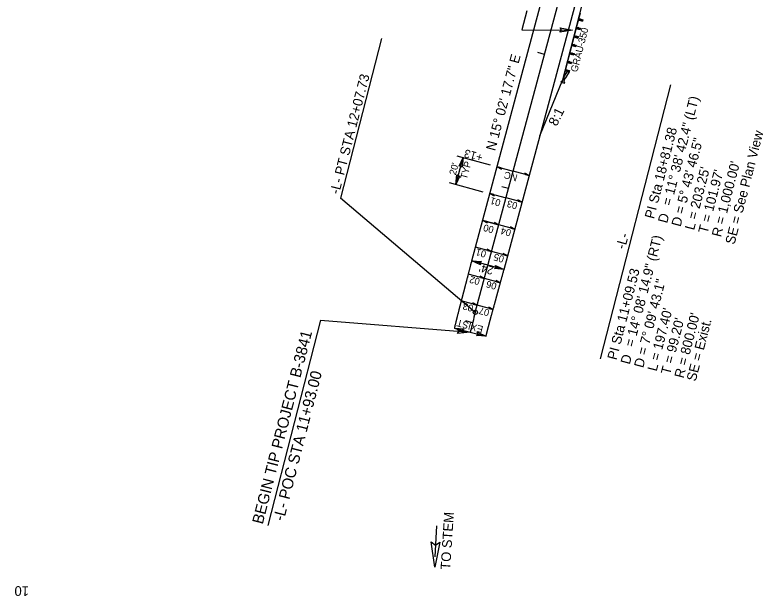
# Model space of a CAD drawing. Extents: x 2078889 to 2079501, y 925860 to 927219.
# Drawn here: x 2078889 to 2079428, y 925860 to 926279 of the extents above; entities that cross this region are included whole.
import ezdxf

# ---------------------------------------------------------------- set-up
doc = ezdxf.new("R2010")
doc.units = 0
for name, color, linetype in [('Default', 7, 'Continuous'), ('Prop Dimension Text', 7, 'Continuous'), ('Prop DSN Text', 7, 'Continuous'), ('Prop EOT', 7, 'Continuous'), ('Prop Guardrail Anchor Unit CELL', 7, 'Continuous'), ('Prop Horizontal Alignment', 7, 'Continuous'), ('Prop Horizontal Alignment Curve and Spiral Data', 7, 'Continuous'), ('Prop Horizontal Alignment Direction Label', 7, 'Continuous'), ('Prop Horizontal Alignment Station Label', 7, 'Continuous'), ('Prop Horizontal Alignment Tick Label', 7, 'Continuous'), ('Prop Horizontal Alignment Tick Small', 7, 'Continuous'), ('Prop Paved Shoulder', 7, 'Continuous'), ('Prop Superelevation  Arrow CELL', 7, 'Continuous'), ('Prop Superelevation Label', 7, 'Continuous'), ('Prop Terminator CELL', 7, 'Continuous'), ('Scratch_Level_1', 7, 'Continuous')]:
    doc.layers.add(name, color=color, linetype=linetype)

msp = doc.modelspace()

# ---------------------------------------------------------------- linework, layer by layer
at = {"layer": 'Prop Dimension Text'}
for p, q in [((2079257.42, 926281.53), (2079253.89, 926267.81)), ((2079253.89, 926267.81), (2079290.34, 926267.6)), ((2079206.31, 926156.54), (2079211.43, 926175.87)), ((2079207.09, 926177.04), (2079230.95, 926170.63)), ((2079201.36, 926157.87), (2079225.76, 926151.31)), ((2079241.03, 926095.44), (2079217.85, 926101.67))]:
    msp.add_line(p, q, dxfattribs=at)
at = {"layer": 'Prop DSN Text'}
msp.add_line((2079205.34, 926053.03), (2079228, 926047.39), dxfattribs=at)
at = {"layer": 'Prop EOT'}
for p, q in [((2079217.85, 926101.67), (2079301.07, 926411.43)), ((2079241.03, 926095.44), (2079324.25, 926405.2))]:
    msp.add_line(p, q, dxfattribs=at)
for points in [[(2079205.34, 926053.03), (2079205.5, 926053.7), (2079205.66, 926054.37), (2079205.82, 926055.03), (2079205.98, 926055.7), (2079206.15, 926056.36), (2079206.31, 926057.03), (2079206.47, 926057.7), (2079206.64, 926058.36), (2079206.8, 926059.03), (2079206.97, 926059.69), (2079207.14, 926060.36), (2079207.3, 926061.02), (2079207.47, 926061.69), (2079207.64, 926062.35), (2079207.81, 926063.02), (2079207.98, 926063.68), (2079208.15, 926064.34), (2079208.32, 926065.01), (2079208.49, 926065.67), (2079208.66, 926066.34), (2079208.83, 926067), (2079209, 926067.66), (2079209.17, 926068.32), (2079209.34, 926068.97), (2079209.51, 926069.62), (2079209.68, 926070.28), (2079209.85, 926070.93), (2079210.02, 926071.58), (2079210.19, 926072.24), (2079210.36, 926072.89), (2079210.53, 926073.55), (2079210.7, 926074.2), (2079210.87, 926074.85), (2079211.04, 926075.51), (2079211.21, 926076.16), (2079211.38, 926076.82), (2079211.55, 926077.47), (2079211.72, 926078.12), (2079211.89, 926078.78), (2079212.06, 926079.43), (2079212.23, 926080.09), (2079212.4, 926080.74), (2079212.57, 926081.39), (2079212.74, 926082.05), (2079212.91, 926082.7), (2079213.08, 926083.36), (2079213.25, 926084.01), (2079213.42, 926084.66), (2079213.59, 926085.32), (2079213.76, 926085.97), (2079213.94, 926086.63), (2079214.11, 926087.28), (2079214.28, 926087.93), (2079214.45, 926088.59), (2079214.62, 926089.24), (2079214.79, 926089.9), (2079214.96, 926090.55), (2079215.13, 926091.2), (2079215.3, 926091.86), (2079215.47, 926092.51), (2079215.64, 926093.16), (2079215.81, 926093.82), (2079215.98, 926094.47), (2079216.15, 926095.13), (2079216.32, 926095.78), (2079216.49, 926096.43), (2079216.66, 926097.09), (2079216.83, 926097.74), (2079217, 926098.4), (2079217.17, 926099.05), (2079217.34, 926099.7), (2079217.51, 926100.36), (2079217.85, 926101.67)], [(2079228, 926047.39), (2079228.16, 926048.04), (2079228.33, 926048.68), (2079228.49, 926049.33), (2079228.66, 926049.97), (2079228.83, 926050.61), (2079228.99, 926051.26), (2079229.16, 926051.9), (2079229.33, 926052.55), (2079229.5, 926053.19), (2079229.67, 926053.84), (2079229.84, 926054.48), (2079230.01, 926055.12), (2079230.18, 926055.77), (2079230.35, 926056.41), (2079230.52, 926057.05), (2079230.69, 926057.7), (2079230.87, 926058.34), (2079231.04, 926058.98), (2079231.22, 926059.62), (2079231.39, 926060.27), (2079231.57, 926060.91), (2079231.74, 926061.55), (2079231.92, 926062.2), (2079232.1, 926062.86), (2079232.28, 926063.51), (2079232.46, 926064.16), (2079232.63, 926064.81), (2079232.81, 926065.46), (2079232.99, 926066.11), (2079233.17, 926066.77), (2079233.35, 926067.42), (2079233.53, 926068.07), (2079233.71, 926068.72), (2079233.88, 926069.37), (2079234.06, 926070.02), (2079234.24, 926070.68), (2079234.42, 926071.33), (2079234.6, 926071.98), (2079234.78, 926072.63), (2079234.96, 926073.28), (2079235.13, 926073.93), (2079235.31, 926074.59), (2079235.49, 926075.24), (2079235.67, 926075.89), (2079235.85, 926076.54), (2079236.03, 926077.19), (2079236.2, 926077.84), (2079236.38, 926078.5), (2079236.56, 926079.15), (2079236.74, 926079.8), (2079236.92, 926080.45), (2079237.1, 926081.1), (2079237.28, 926081.75), (2079237.45, 926082.41), (2079237.63, 926083.06), (2079237.81, 926083.71), (2079237.99, 926084.36), (2079238.17, 926085.01), (2079238.35, 926085.66), (2079238.53, 926086.32), (2079238.7, 926086.97), (2079238.88, 926087.62), (2079239.06, 926088.27), (2079239.24, 926088.92), (2079239.42, 926089.57), (2079239.6, 926090.23), (2079239.78, 926090.88), (2079239.95, 926091.53), (2079240.13, 926092.18), (2079240.31, 926092.83), (2079240.49, 926093.48), (2079240.67, 926094.14), (2079241.03, 926095.44)]]:
    msp.add_spline(points, degree=3, dxfattribs=at)
at = {"layer": 'Prop Guardrail Anchor Unit CELL'}
for p, q in [((2079295.4, 926278.34), (2079283.58, 926233.11)), ((2079294.76, 926275.88), (2079294.51, 926274.92)), ((2079296.21, 926275.5), (2079294.51, 926274.92)), ((2079294.76, 926275.88), (2079297.66, 926275.13)), ((2079295.96, 926274.54), (2079294.76, 926275.88)), ((2079296.21, 926275.5), (2079295.96, 926274.54)), ((2079297.41, 926274.16), (2079296.21, 926275.5)), ((2079294.51, 926274.92), (2079297.41, 926274.16)), ((2079294.51, 926274.92), (2079295.96, 926274.54)), ((2079295.96, 926274.54), (2079297.66, 926275.13)), ((2079297.66, 926275.13), (2079297.41, 926274.16)), ((2079294.64, 926269.4), (2079292.91, 926268.82)), ((2079292.91, 926268.82), (2079295.87, 926268.05)), ((2079293.16, 926269.79), (2079296.12, 926269.02)), ((2079293.16, 926269.79), (2079294.39, 926268.43)), ((2079294.64, 926269.4), (2079294.39, 926268.43)), ((2079294.39, 926268.43), (2079296.12, 926269.02)), ((2079295.87, 926268.05), (2079294.64, 926269.4)), ((2079296.12, 926269.02), (2079295.87, 926268.05)), ((2079293.05, 926263.31), (2079291.32, 926262.72)), ((2079291.32, 926262.72), (2079294.27, 926261.95)), ((2079291.57, 926263.69), (2079294.52, 926262.92)), ((2079291.57, 926263.69), (2079292.79, 926262.34)), ((2079293.05, 926263.31), (2079292.79, 926262.34)), ((2079292.79, 926262.34), (2079294.52, 926262.92)), ((2079294.27, 926261.95), (2079293.05, 926263.31)), ((2079294.52, 926262.92), (2079294.27, 926261.95)), ((2079289.98, 926257.6), (2079289.72, 926256.63)), ((2079291.45, 926257.21), (2079289.72, 926256.63)), ((2079289.72, 926256.63), (2079292.66, 926255.86)), ((2079289.98, 926257.6), (2079292.91, 926256.83)), ((2079289.98, 926257.6), (2079291.19, 926256.24)), ((2079291.45, 926257.21), (2079291.19, 926256.24)), ((2079291.19, 926256.24), (2079292.91, 926256.83)), ((2079292.66, 926255.86), (2079291.45, 926257.21)), ((2079292.91, 926256.83), (2079292.66, 926255.86)), ((2079289.9, 926251.1), (2079288.13, 926250.53)), ((2079288.13, 926250.53), (2079291.17, 926249.74)), ((2079288.38, 926251.5), (2079291.42, 926250.71)), ((2079288.38, 926251.5), (2079289.65, 926250.14)), ((2079289.9, 926251.1), (2079289.65, 926250.14)), ((2079289.65, 926250.14), (2079291.42, 926250.71)), ((2079291.17, 926249.74), (2079289.9, 926251.1)), ((2079291.42, 926250.71), (2079291.17, 926249.74)), ((2079288.24, 926245.02), (2079286.54, 926244.43)), ((2079286.54, 926244.43), (2079289.44, 926243.68)), ((2079286.79, 926245.4), (2079289.69, 926244.64)), ((2079286.79, 926245.4), (2079287.99, 926244.06)), ((2079288.24, 926245.02), (2079287.99, 926244.06)), ((2079287.99, 926244.06), (2079289.69, 926244.64)), ((2079289.44, 926243.68), (2079288.24, 926245.02)), ((2079289.69, 926244.64), (2079289.44, 926243.68)), ((2079286.42, 926237.95), (2079283.7, 926233.6)), ((2079286.68, 926238.92), (2079284.94, 926238.34)), ((2079284.94, 926238.34), (2079287.91, 926237.56)), ((2079287.91, 926237.56), (2079285.15, 926233.22)), ((2079285.2, 926239.31), (2079288.16, 926238.53)), ((2079285.2, 926239.31), (2079286.42, 926237.95)), ((2079286.68, 926238.92), (2079286.42, 926237.95)), ((2079286.42, 926237.95), (2079288.16, 926238.53)), ((2079287.91, 926237.56), (2079286.68, 926238.92)), ((2079288.16, 926238.53), (2079287.91, 926237.56)), ((2079283.64, 926233.06), (2079283.09, 926231.09)), ((2079283.45, 926232.63), (2079285.15, 926233.22)), ((2079283.45, 926232.63), (2079284.9, 926232.25)), ((2079284.23, 926232.9), (2079283.64, 926233.06)), ((2079283.7, 926233.6), (2079285.15, 926233.22)), ((2079284.9, 926232.25), (2079283.7, 926233.6)), ((2079284.82, 926232.73), (2079284.23, 926232.9)), ((2079284.26, 926230.76), (2079284.82, 926232.73)), ((2079285.15, 926233.22), (2079284.9, 926232.25)), ((2079285.15, 926233.22), (2079285.03, 926232.73)), ((2079283.09, 926231.09), (2079281.94, 926230.19)), ((2079281.94, 926230.19), (2079284.77, 926229.4)), ((2079284.77, 926229.4), (2079284.26, 926230.76))]:
    msp.add_line(p, q, dxfattribs=at)
at = {"layer": 'Prop Horizontal Alignment'}
msp.add_line((2079220.28, 926064.49), (2079368.62, 926616.59), dxfattribs=at)
msp.add_arc((2079992.89, 925856.91), 800, 164.96174, 166.01636, dxfattribs=at)
at = {"layer": 'Prop Horizontal Alignment Curve and Spiral Data'}
for p, q in [((2079152.69, 926261.62), (2079123.14, 926146.7)), ((2079310.51, 926030.96), (2079361.22, 926228.21)), ((2079108.8, 926058.75), (2079070.83, 925911.09))]:
    msp.add_line(p, q, dxfattribs=at)
msp.add_lwpolyline([(2079108.8, 926058.75), (2079216.59, 926050.23)], dxfattribs=at)
msp.add_lwpolyline([(2079207.74, 926052.48), (2079216.59, 926050.23), (2079207.45, 926049.35), (2079208.72, 926050.85)], close=True, dxfattribs=at)
at = {"layer": 'Prop Horizontal Alignment Direction Label'}
msp.add_line((2079191.47, 925888.61), (2079192.53, 925910.74), dxfattribs=at)
at = {"layer": 'Prop Horizontal Alignment Station Label'}
msp.add_line((2079220.28, 926064.49), (2079123.14, 926146.7), dxfattribs=at)
msp.add_circle((2079220.28, 926064.49), 1.5, dxfattribs=at)
at = {"layer": 'Prop Horizontal Alignment Tick Small'}
for p, q in [((2079270.17, 926250.18), (2079265.34, 926251.47)), ((2079244.23, 926153.6), (2079239.4, 926154.9)), ((2079218.32, 926057.02), (2079213.47, 926058.27))]:
    msp.add_line(p, q, dxfattribs=at)
at = {"layer": 'Prop Paved Shoulder'}
msp.add_line((2079266.83, 926191.49), (2079283.32, 926231.98), dxfattribs=at)
msp.add_lwpolyline([(2079295.72, 926279.55), (2079294.45, 926274.85), (2079294.3, 926274.27), (2079293.79, 926272.27), (2079283.32, 926231.98)], dxfattribs=at)
at = {"layer": 'Prop Superelevation  Arrow CELL'}
for p, q in [((2079236.01, 926169.27), (2079247.6, 926166.15)), ((2079259.19, 926163.04), (2079247.6, 926166.15)), ((2079230.82, 926149.95), (2079242.41, 926146.84)), ((2079254, 926143.73), (2079242.41, 926146.84)), ((2079237.22, 926127.52), (2079225.63, 926130.64)), ((2079225.63, 926130.64), (2079237.22, 926127.52)), ((2079248.81, 926124.41), (2079237.22, 926127.52)), ((2079232.03, 926108.21), (2079220.44, 926111.32)), ((2079243.62, 926105.1), (2079232.03, 926108.21)), ((2079226.84, 926088.89), (2079215.25, 926092.01)), ((2079238.43, 926085.78), (2079226.84, 926088.89)), ((2079221.65, 926069.58), (2079210.06, 926072.69)), ((2079233.24, 926066.47), (2079221.65, 926069.58))]:
    msp.add_line(p, q, dxfattribs=at)
for points in [[(2079236.01, 926169.27), (2079239.18, 926167.59), (2079238.86, 926168.5)], [(2079259.19, 926163.04), (2079256.02, 926164.72), (2079256.34, 926163.81)], [(2079230.82, 926149.95), (2079233.99, 926148.27), (2079233.67, 926149.19)], [(2079254, 926143.73), (2079250.83, 926145.41), (2079251.15, 926144.49)], [(2079225.63, 926130.64), (2079228.8, 926128.96), (2079228.48, 926129.87)], [(2079237.22, 926127.52), (2079234.05, 926129.21), (2079234.37, 926128.29)], [(2079248.81, 926124.41), (2079245.64, 926126.09), (2079245.96, 926125.18)], [(2079232.03, 926108.21), (2079228.86, 926109.89), (2079229.18, 926108.98)], [(2079243.62, 926105.1), (2079240.45, 926106.78), (2079240.77, 926105.86)], [(2079226.84, 926088.89), (2079223.67, 926090.58), (2079223.99, 926089.66)], [(2079238.43, 926085.78), (2079235.26, 926087.46), (2079235.58, 926086.55)], [(2079221.65, 926069.58), (2079218.48, 926071.26), (2079218.8, 926070.35)], [(2079233.24, 926066.47), (2079230.07, 926068.15), (2079230.39, 926067.23)]]:
    msp.add_lwpolyline(points, close=True, dxfattribs=at)
at = {"layer": 'Prop Terminator CELL'}
for points in [[(2079281.35, 926269.2), (2079290.34, 926267.6), (2079281.28, 926266.05), (2079282.44, 926267.65)], [(2079208.58, 926169.64), (2079211.43, 926175.87), (2079210.85, 926169), (2079209.91, 926170.15)], [(2079209.16, 926162.77), (2079206.31, 926156.54), (2079206.89, 926163.41), (2079207.83, 926162.27)], [(2079224.06, 926098.79), (2079217.85, 926101.67), (2079224.71, 926101.06), (2079223.57, 926100.13)], [(2079234.81, 926098.31), (2079241.03, 926095.44), (2079234.16, 926096.04), (2079235.3, 926096.98)], [(2079211.61, 926050.27), (2079205.34, 926053.03), (2079212.21, 926052.56), (2079211.09, 926051.6)], [(2079221.73, 926050.15), (2079228, 926047.39), (2079221.12, 926047.87), (2079222.25, 926048.82)], [(2079194.74, 925898.96), (2079191.1, 925881.07), (2079188.45, 925899.25), (2079191.58, 925896.86)]]:
    msp.add_lwpolyline(points, close=True, dxfattribs=at)
at = {"layer": 'Scratch_Level_1'}
msp.add_line((2079282.79, 926229.95), (2079295.4, 926278.34), dxfattribs=at)
msp.add_lwpolyline([(2079295.4, 926278.34), (2079322.68, 926386.21), (2079327.54, 926404.32)], dxfattribs=at)

# ---------------------------------------------------------------- texts
at = {"layer": 'Default'}
for s, p in [('BEGIN TIP PROJECT B-3841', (2079067.12, 925911.54)), ('-L- POC STA 11+93.00', (2079082.28, 925913.76))]:
    msp.add_text(s, height=8, rotation=75.5809, dxfattribs=at).set_placement(p)
at = {"layer": 'Prop Dimension Text'}
for s, height, rotation, p in [('+13', 5.95, 164.5572, (2079226.25, 926178.35)), ('TYP', 5, 75.1911, (2079214.23, 926159.88)), ("20'", 5, 75.1911, (2079206.17, 926162.95)), ("24'", 5.95, 165.5327, (2079233.97, 926097.13)), ('EXIST', 5, 164.5572, (2079226.38, 926054.34))]:
    msp.add_text(s, height=height, rotation=rotation, dxfattribs=at).set_placement(p)
at = {"layer": 'Prop DSN Text'}
msp.add_text('8:1', height=7, rotation=64.0268, dxfattribs=at).set_placement((2079278.92, 926197.98))
at = {"layer": 'Prop Guardrail Anchor Unit CELL'}
msp.add_text('GRAU-350', height=5, rotation=75.5809, dxfattribs=at).set_placement((2079293.69, 926237.01))
at = {"layer": 'Prop Horizontal Alignment Curve and Spiral Data'}
for s, rotation, p in [('= 11%%d 38\' 42.4" (LT)', 75.5812, (2079361.4, 926140.75)), ('PI Sta 18+81.38', 75.5812, (2079348.97, 926131.37)), ('SE = See Plan View', 75.5812, (2079407, 926112.9)), ('D = 5%%d 43\' 46.5"', 75.5812, (2079368.17, 926125.74)), ("R = 1,000.00'", 75.5812, (2079397.23, 926118.27)), ("L = 203.25'", 75.5812, (2079377.86, 926123.25)), ("T = 101.97'", 75.5812, (2079387.54, 926120.76)), ('D', 75.5812, (2079358.49, 926128.23)), ('-L-', 74.5572, (2079328.05, 926109.5)), ('= 14%%d 08\' 14.9" (RT)', 75.5812, (2079334.47, 926039.14)), ('PI Sta 11+09.53', 75.5812, (2079322.03, 926029.77)), ('D = 7%%d 09\' 43.1"', 75.5812, (2079341.24, 926024.13)), ("L = 197.40'", 75.5812, (2079350.92, 926021.64)), ("T = 99.20'", 75.5812, (2079360.61, 926019.15)), ("R = 800.00'", 75.5812, (2079370.29, 926016.66)), ('SE = Exist.', 75.5812, (2079379.09, 926014.4)), ('D', 75.5812, (2079331.55, 926026.62))]:
    msp.add_text(s, height=7, rotation=rotation, dxfattribs=at).set_placement(p)
at = {"layer": 'Prop Horizontal Alignment Direction Label'}
for s, rotation, p in [('N 15%%d 02\' 17.7" E', 74.9617, (2079234.54, 926180.29)), ('TO STEM', 86.2787, (2079202.2, 925879.01))]:
    msp.add_text(s, height=7, rotation=rotation, dxfattribs=at).set_placement(p)
at = {"layer": 'Prop Horizontal Alignment Station Label'}
msp.add_text('-L- PT STA 12+07.73', height=7, rotation=75.5809, dxfattribs=at).set_placement((2079122.16, 926149.11))
at = {"layer": 'Prop Horizontal Alignment Tick Label'}
msp.add_text('10', height=7, rotation=179.0992, dxfattribs=at).set_placement((2078898.77, 925867.29))
at = {"layer": 'Prop Superelevation Label'}
for s, p in [('NC', (2079251.09, 926163.47)), ('01', (2079238.97, 926145.46)), ('03', (2079251.12, 926143.34)), ('00', (2079234.05, 926126.09)), ('04', (2079246.55, 926123.85)), ('01', (2079228.6, 926108.57)), ('05', (2079241.46, 926104.94)), ('02', (2079224.06, 926088.78)), ('06', (2079236.12, 926085.42)), ('03', (2079219.25, 926069.54)), ('07', (2079230.87, 926066.33))]:
    msp.add_text(s, height=5, rotation=164.7434, dxfattribs=at).set_placement(p)

doc.saveas('drawing.dxf')
